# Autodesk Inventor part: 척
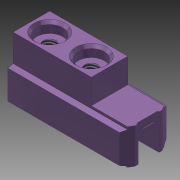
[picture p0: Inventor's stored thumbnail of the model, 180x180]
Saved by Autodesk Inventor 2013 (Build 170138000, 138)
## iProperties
Created: 2023-03
Part Number: 척
Material: 강철, 탄소
Document SubType Name: Modeling
Designer: mdu-01
Density: 1 g/cm^3
Author: mdu-01
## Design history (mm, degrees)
sketch "스케치1"
  geometry: L1 (0, 0)-(23, 0); L2 (12.536, -7)-(12, -9); L3 (12, -9)-(1, -9); L4 (1, -9)-(0.464, -7); L5 (23, -7)-(12.536, -7); L6 (0.464, -7)-(0, -7); L7 (12.536, 7)-(12, 9); L8 (12, 9)-(1, 9); L9 (1, 9)-(0.464, 7); L10 (23, 7)-(12.536, 7); L11 (0.464, 7)-(0, 7); L12 (0, 7)-(0, -7); L13 (23, 7)-(23, -7); L14 (6.5, 9)-(6.5, -9)
  constraints: 28 end point, 6 symmetric about line, 4 parallel, 2 midpoint, 2 perpendicular, 2 vertical alignment, 1 equal length, 1 horizontal, 1 other
  dimensions: "d0" = 23 distance of L1.start L1.end; "d1" = 1 horizontal distance of L3.end L6.end; "d2" = 11 distance of L2.end L3.end; "d3" = 30 deg angle of L4 L2; "d5" = 14 distance between parallel lines of L5 L10; "d6" = 18 distance between parallel lines of L3 L8
extrude "돌출1" new body sketch "스케치1" distance "d7" = 45; taper "d8" = 0 deg
sketch "스케치2"
  geometry: L1 (0, 16)-(45, 16) reference; L2 (0, -2)-(45, -2) reference; L3 (45, 16)-(45, 14) reference; L4 (45, 14)-(45, 0) reference; L5 (45, 0)-(45, -2) reference; L6 (42.804, 16)-(45, 12.196); L7 (42.804, -2)-(45, 1.804); L8 (0, 0)-(0, 14) reference; 3 further points
  constraints: 6 point on line, 4 end point, 1 horizontal alignment, 1 midpoint, 1 vertical alignment
  dimensions: "d9" = 3 distance from line of point (48, 7) L5; "d10" = 120 deg angle of L7 L6
extrude "돌출2" cut sketch "스케치2" stored distance "d11" = 45; taper "d12" = 0 deg
sketch "스케치3"
  geometry: L1 (-7, 23)-(7, 23); L2 (7, 23)-(7, 13.5); L3 (7, 13.5)-(-7, 13.5); L4 (-7, 13.5)-(-7, 23); L5 (5.196, 23)-(-5.196, 23) reference; L6 (-7, 12.536)-(-7, 23) reference; 2 further points
  constraints: 8 end point, 2 midpoint, 2 parallel, 1 collinear, 1 horizontal, 1 perpendicular
  dimensions: "d13" = 9.5 distance between parallel lines of L3 L1
extrude "돌출3" cut sketch "스케치3" distance "d15" = 15; taper "d16" = 0 deg
sketch "스케치4"
  geometry: L1 (30, 13.5)-(43.959, 13.5) reference; L2 (43.959, 13.5)-(45, 13.5) reference; L3 (45, 0)-(45, 13.5) reference; L4 (43.959, 0)-(45, 0) reference; L5 (0, 0)-(43.959, 0) reference; L6 (44.5, 13.5)-(31, 0); L7 (45, 11.172)-(33.828, 0); L8 (45, 8.343)-(36.657, 0); L9 (44.5, 13.5)-(45, 13.5); L10 (45, 11.172)-(45, 13.5)
  constraints: 10 end point, 6 point on line, 2 parallel, 1 collinear, 1 perpendicular
  dimensions: "d17" = 45 deg angle of L6 L1; "d18" = 14 distance from line of L6.end L3; "d19" = 2 distance between parallel lines of L7 L6; "d20" = 2 distance between parallel lines of L8 L7
extrude "돌출4" cut sketch "스케치4" stored distance "d21" = 8; taper "d22" = 0 deg
extrude "돌출5" cut sketch "스케치4" stored distance "d23" = 4; taper "d24" = 0 deg
fillet "모깎기1" dims "d25" = 0.5
sketch "스케치5"
  geometry: L1 (0, 0)-(0, 14) reference; C1 r 5 at (7, 7); C2 r 5 at (23, 7); 2 further points
  constraints: 2 centre point, 2 horizontal alignment, 1 equal radius, 1 midpoint
  dimensions: "d26" = 10 diameter of C1; "d27" = 7 distance from line of C1.centre L1; "d28" = 16 distance of C2.centre C1.centre
extrude "돌출6" cut sketch "스케치5" distance "d29" = 4; taper "d30" = 0 deg
chamfer "모따기1" distance "d31" = 1; stored, may be unused: second distance "d32" = 2, angle "d33" = 45 deg
sketch "스케치6"
  geometry: C1 r 5 at (0, 0) reference; C2 r 5 at (16, 0) reference; 1 further point
hole "구멍1" sketch "스케치6" at (0, 0), (16, 0) diameter "d34" = 4.917; stored, may be unused: countersink angle "d38" = 90 deg, drill point angle "d40" = 118 deg; dims "d35" = 12, "d36" = 4, "d37" = 2, "d39" = 14
node "솔리드1"
other parameters: "d4" = 2
